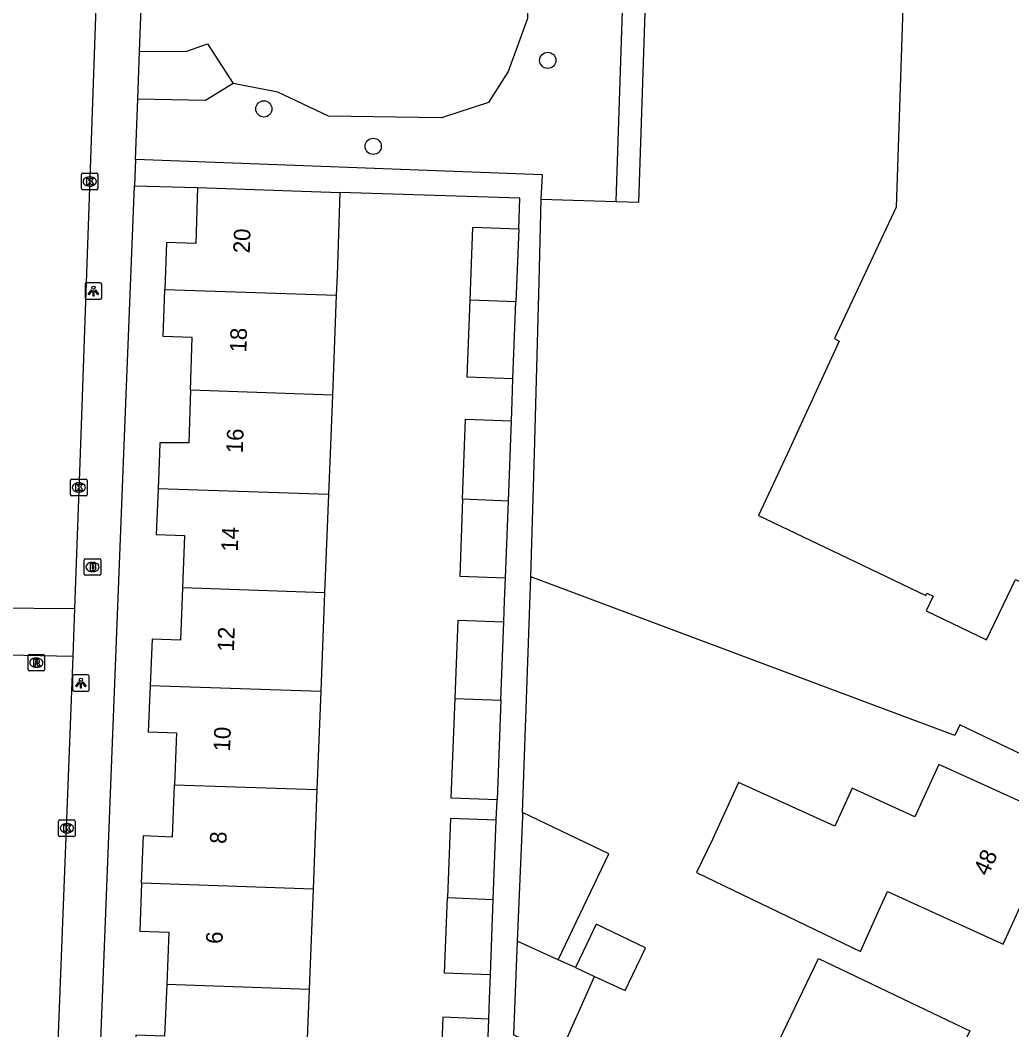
# Model space of a CAD drawing. Extents: x 161355 to 162026, y 386504 to 387459.
# Drawn here: x 161585.7 to 161645.5, y 386965.2 to 387026.1 of the extents above; entities that cross this region are included whole.
import ezdxf

# ---------------------------------------------------------------- set-up
doc = ezdxf.new("R2010")
doc.units = 0
for name, color, linetype in [('IMGEO_Boom', 7, 'Continuous'), ('IMGEO_Brandkraan', 7, 'Continuous'), ('IMGEO_Groenvoorziening', 7, 'Continuous'), ('IMGEO_Kolk', 7, 'Continuous'), ('IMGEO_Lichtpunt', 7, 'Continuous'), ('IMGEO_Pand', 7, 'Continuous'), ('IMGEO_Pand_nummerreeks', 7, 'Continuous'), ('IMGEO_Rijbaan_lokaal_open', 7, 'Continuous'), ('IMGEO_Rioolput', 7, 'Continuous'), ('IMGEO_Voetpad_open', 7, 'Continuous')]:
    doc.layers.add(name, color=color, linetype=linetype)

msp = doc.modelspace()

# ---------------------------------------------------------------- linework, layer by layer
at = {"layer": 'IMGEO_Boom'}
for centre in [(161617.488, 387023.712), (161600.362, 387020.785), (161606.959, 387018.529)]:
    msp.add_circle(centre, 0.489, dxfattribs=at)
at = {"layer": 'IMGEO_Brandkraan'}
for p, q in [((161589.526, 386992.715), (161589.526, 386993.567)), ((161589.601, 386993.641), (161590.453, 386993.641)), ((161590.014, 386993.421), (161590.039, 386993.421)), ((161590.527, 386993.567), (161590.527, 386992.715)), ((161590.453, 386992.641), (161589.601, 386992.641)), ((161590.037, 386992.861), (161590.012, 386992.861))]:
    msp.add_line(p, q, dxfattribs=at)
for points in [[(161589.526, 386992.715), (161589.526, 386993.567)], [(161589.601, 386993.641), (161590.453, 386993.641)], [(161589.874, 386993.341), (161589.874, 386992.941), (161590.087, 386992.941)], [(161590.105, 386993.341), (161589.874, 386993.341)], [(161590.053, 386993.26), (161589.999, 386993.26), (161589.999, 386993.184)], [(161589.999, 386993.184), (161590.052, 386993.184)], [(161590.061, 386993.108), (161589.999, 386993.108), (161589.999, 386993.027)], [(161590.527, 386993.567), (161590.527, 386992.715)], [(161590.453, 386992.641), (161589.601, 386992.641)], [(161589.999, 386993.027), (161590.061, 386993.027)]]:
    msp.add_lwpolyline(points, dxfattribs=at)
for centre, radius, start, end in [((161589.603, 386993.565), 0.0765, 91.55205, 178.44795), ((161589.603, 386993.565), 0.0765, 91.55205, 178.44795), ((161590.054, 386993.222), 0.0379, 267.82845, 90.93552), ((161590.062, 386993.067), 0.0404, 269.87594, 90.50774), ((161590.109, 386993.196), 0.145, 59.4692, 91.53667), ((161590.134, 386993.243), 0.0922, 285.51372, 58.15012), ((161590.139, 386993.051), 0.105, 301.31148, 78.98903), ((161590.451, 386993.565), 0.0765, 1.55205, 88.44795), ((161590.451, 386993.565), 0.0765, 1.55205, 88.44795), ((161589.603, 386992.717), 0.0765, 181.55205, 268.44795), ((161589.603, 386992.717), 0.0765, 181.55205, 268.44795), ((161590.093, 386993.192), 0.251, 268.66757, 293.53466), ((161590.451, 386992.717), 0.0765, 271.55205, 358.44795), ((161590.451, 386992.717), 0.0765, 271.55205, 358.44795)]:
    msp.add_arc(centre, radius, start, end, dxfattribs=at)
for centre, major_axis, ratio, start_param, end_param in [((161590.013, 386993.141), (-0.387, 0.002), 0.722429, 4.712389, 7.853982), ((161590.038, 386993.141), (-0.39, 0.002), 0.717154, 1.570796, 4.712389)]:
    msp.add_ellipse(centre, major_axis=major_axis, ratio=ratio, start_param=start_param, end_param=end_param, dxfattribs=at)
at = {"layer": 'IMGEO_Groenvoorziening'}
for points in [[(161622.376, 387038.848), (161621.592, 387015.198)], [(161616.414, 387030.911), (161616.263, 387026.241), (161615.091, 387023.044), (161613.923, 387021.167), (161611.08, 387020.252), (161604.264, 387020.353), (161601.199, 387021.802), (161598.502, 387022.32)]]:
    msp.add_lwpolyline(points, dxfattribs=at)
at = {"layer": 'IMGEO_Kolk'}
for p, q in [((161589.354, 387015.977), (161589.354, 387016.829)), ((161589.429, 387016.903), (161590.281, 387016.903)), ((161590.355, 387016.829), (161590.355, 387015.977)), ((161589.842, 387016.683), (161589.867, 387016.683)), ((161590.281, 387015.903), (161589.429, 387015.903)), ((161589.865, 387016.123), (161589.84, 387016.123)), ((161588.702, 386997.516), (161588.702, 386998.368)), ((161588.777, 386998.442), (161589.629, 386998.442)), ((161589.19, 386998.222), (161589.215, 386998.222)), ((161589.703, 386998.368), (161589.703, 386997.516)), ((161589.629, 386997.442), (161588.777, 386997.442)), ((161589.213, 386997.662), (161589.188, 386997.662)), ((161588.054, 386977.877), (161588.906, 386977.877)), ((161587.979, 386976.951), (161587.979, 386977.803)), ((161588.467, 386977.657), (161588.492, 386977.657)), ((161588.98, 386977.803), (161588.98, 386976.951)), ((161588.906, 386976.877), (161588.054, 386976.877)), ((161588.49, 386977.097), (161588.465, 386977.097))]:
    msp.add_line(p, q, dxfattribs=at)
for points in [[(161589.354, 387015.977), (161589.354, 387016.829)], [(161589.429, 387016.903), (161590.281, 387016.903)], [(161590.355, 387016.829), (161590.355, 387015.977)], [(161589.675, 387016.603), (161589.798, 387016.603), (161589.798, 387016.452), (161589.928, 387016.603), (161590.092, 387016.603), (161589.946, 387016.452), (161590.099, 387016.203), (161589.947, 387016.203), (161589.862, 387016.367), (161589.798, 387016.3), (161589.798, 387016.203), (161589.675, 387016.203), (161589.675, 387016.603)], [(161590.281, 387015.903), (161589.429, 387015.903)], [(161588.702, 386997.516), (161588.702, 386998.368)], [(161588.777, 386998.442), (161589.629, 386998.442)], [(161589.023, 386998.142), (161589.146, 386998.142), (161589.146, 386997.991), (161589.276, 386998.142), (161589.44, 386998.142), (161589.294, 386997.991), (161589.447, 386997.742), (161589.295, 386997.742), (161589.21, 386997.906), (161589.146, 386997.839), (161589.146, 386997.742), (161589.023, 386997.742), (161589.023, 386998.142)], [(161589.703, 386998.368), (161589.703, 386997.516)], [(161589.629, 386997.442), (161588.777, 386997.442)], [(161588.054, 386977.877), (161588.906, 386977.877)], [(161587.979, 386976.951), (161587.979, 386977.803)], [(161588.3, 386977.577), (161588.423, 386977.577), (161588.423, 386977.426), (161588.553, 386977.577), (161588.717, 386977.577), (161588.571, 386977.426), (161588.724, 386977.177), (161588.572, 386977.177), (161588.487, 386977.341), (161588.423, 386977.274), (161588.423, 386977.177), (161588.3, 386977.177), (161588.3, 386977.577)], [(161588.98, 386977.803), (161588.98, 386976.951)], [(161588.906, 386976.877), (161588.054, 386976.877)]]:
    msp.add_lwpolyline(points, dxfattribs=at)
for centre, start, end in [((161589.431, 387016.827), 91.55205, 178.44795), ((161589.431, 387016.827), 91.55205, 178.44795), ((161590.279, 387016.827), 1.55205, 88.44795), ((161590.279, 387016.827), 1.55205, 88.44795), ((161589.431, 387015.979), 181.55205, 268.44795), ((161589.431, 387015.979), 181.55205, 268.44795), ((161590.279, 387015.979), 271.55205, 358.44795), ((161590.279, 387015.979), 271.55205, 358.44795), ((161588.779, 386998.366), 91.55205, 178.44795), ((161588.779, 386998.366), 91.55205, 178.44795), ((161589.627, 386998.366), 1.55205, 88.44795), ((161589.627, 386998.366), 1.55205, 88.44795), ((161588.779, 386997.518), 181.55205, 268.44795), ((161588.779, 386997.518), 181.55205, 268.44795), ((161589.627, 386997.518), 271.55205, 358.44795), ((161589.627, 386997.518), 271.55205, 358.44795), ((161588.056, 386977.801), 91.55205, 178.44795), ((161588.056, 386977.801), 91.55205, 178.44795), ((161588.904, 386977.801), 1.55205, 88.44795), ((161588.904, 386977.801), 1.55205, 88.44795), ((161588.056, 386976.953), 181.55205, 268.44795), ((161588.056, 386976.953), 181.55205, 268.44795), ((161588.904, 386976.953), 271.55205, 358.44795), ((161588.904, 386976.953), 271.55205, 358.44795)]:
    msp.add_arc(centre, 0.0765, start, end, dxfattribs=at)
for centre, major_axis, ratio, start_param, end_param in [((161589.841, 387016.403), (-0.387, 0.002), 0.722429, 4.712389, 7.853982), ((161589.866, 387016.403), (-0.39, 0.002), 0.717154, 1.570796, 4.712389), ((161589.189, 386997.942), (-0.387, 0.002), 0.722429, 4.712389, 7.853982), ((161589.214, 386997.942), (-0.39, 0.002), 0.717154, 1.570796, 4.712389), ((161588.466, 386977.377), (-0.387, 0.002), 0.722429, 4.712389, 7.853982), ((161588.491, 386977.377), (-0.39, 0.002), 0.717154, 1.570796, 4.712389)]:
    msp.add_ellipse(centre, major_axis=major_axis, ratio=ratio, start_param=start_param, end_param=end_param, dxfattribs=at)
at = {"layer": 'IMGEO_Lichtpunt'}
for p, q in [((161589.583, 387010.2), (161589.583, 387009.393)), ((161589.583, 387010.2), (161589.583, 387009.393)), ((161590.485, 387010.295), (161589.677, 387010.295)), ((161590.485, 387010.295), (161589.677, 387010.295)), ((161590.579, 387009.393), (161590.579, 387010.2)), ((161590.579, 387009.393), (161590.579, 387010.2)), ((161589.677, 387009.299), (161590.485, 387009.299)), ((161589.677, 387009.299), (161590.485, 387009.299)), ((161588.825, 386986.544), (161588.825, 386985.737)), ((161588.825, 386986.544), (161588.825, 386985.737)), ((161589.727, 386986.639), (161588.919, 386986.639)), ((161589.727, 386986.639), (161588.919, 386986.639)), ((161589.821, 386985.737), (161589.821, 386986.544)), ((161589.821, 386985.737), (161589.821, 386986.544)), ((161588.919, 386985.643), (161589.727, 386985.643)), ((161588.919, 386985.643), (161589.727, 386985.643))]:
    msp.add_line(p, q, dxfattribs=at)
for points in [[(161589.957, 387009.864), (161589.996, 387009.836), (161589.808, 387009.574), (161589.77, 387009.601), (161589.957, 387009.864)], [(161590.059, 387009.816), (161590.106, 387009.816), (161590.106, 387009.494), (161590.059, 387009.494), (161590.059, 387009.816)], [(161590.169, 387009.836), (161590.207, 387009.863), (161590.394, 387009.601), (161590.355, 387009.573), (161590.169, 387009.836)], [(161589.199, 386986.208), (161589.238, 386986.18), (161589.05, 386985.918), (161589.012, 386985.945), (161589.199, 386986.208)], [(161589.301, 386986.16), (161589.348, 386986.16), (161589.348, 386985.838), (161589.301, 386985.838), (161589.301, 386986.16)], [(161589.411, 386986.18), (161589.449, 386986.207), (161589.636, 386985.945), (161589.597, 386985.917), (161589.411, 386986.18)]]:
    msp.add_lwpolyline(points, dxfattribs=at)
for centre in [(161590.082, 387009.998), (161589.324, 386986.342)]:
    msp.add_circle(centre, 0.0994, dxfattribs=at)
for centre, start, end in [((161589.677, 387010.2), 90, 180), ((161589.677, 387010.2), 90, 180), ((161590.485, 387010.2), 0, 90), ((161590.485, 387010.2), 0, 90), ((161589.677, 387009.393), 180, 270), ((161589.677, 387009.393), 180, 270), ((161590.485, 387009.393), 270, 0), ((161590.485, 387009.393), 270, 360), ((161588.919, 386986.544), 90, 180), ((161588.919, 386986.544), 90, 180), ((161589.727, 386986.544), 0, 90), ((161589.727, 386986.544), 0, 90), ((161588.919, 386985.737), 180, 270), ((161588.919, 386985.737), 180, 270), ((161589.727, 386985.737), 270, 0), ((161589.727, 386985.737), 270, 360)]:
    msp.add_arc(centre, 0.0946, start, end, dxfattribs=at)
at = {"layer": 'IMGEO_Pand'}
for points in [[(161621.592, 387015.198), (161622.991, 387015.152), (161623.69, 387036.251)], [(161639.028, 387030.532), (161638.508, 387014.846), (161634.791, 387006.94), (161635.073, 387006.762), (161631.945, 387000), (161630.209, 386996.251), (161636.023, 386993.468), (161640.299, 386991.421), (161640.365, 386991.559), (161640.742, 386991.379), (161640.319, 386990.494), (161643.964, 386988.749), (161645.705, 386992.384), (161649.5, 386990.567), (161654.01, 386988.408), (161653.819, 386988.01), (161653.371, 386988.225), (161651.645, 386984.62), (161652.067, 386984.418), (161649.94, 386979.976), (161642.34, 386983.614), (161642.038, 386982.983), (161637.356, 386984.735), (161616.468, 386992.553)], [(161596.365, 387016.033), (161596.254, 387012.669), (161594.482, 387012.728), (161594.389, 387009.89)], [(161596.365, 387016.033), (161604.946, 387015.749)], [(161604.946, 387015.749), (161604.776, 387010.752), (161604.729, 387009.538)], [(161616.468, 386992.553), (161616.68, 387000), (161616.974, 387010.349), (161617.094, 387015.347)], [(161617.094, 387015.347), (161621.592, 387015.198)], [(161612.806, 387009.251), (161612.973, 387013.654), (161615.735, 387013.549)], [(161615.735, 387013.549), (161615.568, 387009.14)], [(161595.932, 387003.812), (161596.037, 387006.992), (161594.295, 387007.05), (161594.389, 387009.89)], [(161594.389, 387009.89), (161604.729, 387009.538)], [(161604.729, 387009.538), (161604.494, 387003.521)], [(161615.392, 387004.487), (161612.63, 387004.591), (161612.806, 387009.251)], [(161615.568, 387009.14), (161612.806, 387009.251)], [(161615.392, 387004.487), (161615.568, 387009.14)], [(161595.932, 387003.812), (161595.827, 387000.633), (161594.088, 387000.625), (161594.064, 387000), (161593.981, 386997.865)], [(161604.494, 387003.521), (161595.932, 387003.812)], [(161604.494, 387003.521), (161604.356, 387000), (161604.259, 386997.515)], [(161612.351, 386997.232), (161612.534, 387002.06), (161615.297, 387001.956)], [(161615.114, 386997.121), (161615.297, 387001.956)], [(161593.981, 386997.865), (161593.873, 386995.106), (161595.582, 386995.037), (161595.454, 386991.878)], [(161604.259, 386997.515), (161593.981, 386997.865)], [(161604.259, 386997.515), (161604.027, 386991.586)], [(161612.351, 386997.232), (161612.176, 386992.596), (161614.938, 386992.492)], [(161615.114, 386997.121), (161612.351, 386997.232)], [(161614.938, 386992.492), (161615.114, 386997.121)], [(161595.454, 386991.878), (161595.327, 386988.721), (161593.616, 386988.79), (161593.503, 386985.995)], [(161604.027, 386991.586), (161595.454, 386991.878)], [(161604.027, 386991.586), (161603.795, 386985.645)], [(161611.896, 386985.213), (161612.075, 386989.938), (161614.838, 386989.834)], [(161614.659, 386985.102), (161614.838, 386989.834)], [(161593.503, 386985.995), (161593.391, 386983.201), (161595.1, 386983.132), (161594.973, 386980)], [(161593.503, 386985.995), (161603.795, 386985.645)], [(161603.795, 386985.645), (161603.563, 386979.708)], [(161614.431, 386979.092), (161611.669, 386979.203), (161611.896, 386985.213)], [(161611.896, 386985.213), (161614.659, 386985.102)], [(161614.659, 386985.102), (161614.431, 386979.092)], [(161648.381, 386977.91), (161643.83, 386979.98), (161641.076, 386981.232), (161639.638, 386978.068), (161635.853, 386979.789), (161634.812, 386977.499), (161628.998, 386980.143), (161627.426, 386976.709), (161626.462, 386974.71), (161636.348, 386969.941), (161637.37, 386972.188), (161637.992, 386973.556), (161644.961, 386970.388), (161648.381, 386977.91)], [(161592.989, 386974.058), (161593.105, 386976.94), (161594.847, 386976.869), (161594.973, 386980)], [(161594.973, 386980), (161603.563, 386979.708)], [(161603.563, 386979.708), (161603.329, 386973.706)], [(161614.384, 386977.857), (161611.622, 386977.961), (161611.441, 386973.194)], [(161614.204, 386973.082), (161614.384, 386977.857)], [(161615.966, 386978.319), (161615.957, 386978.067), (161615.651, 386970.572)], [(161618.108, 386969.444), (161621.174, 386975.836), (161615.966, 386978.319)], [(161592.989, 386974.058), (161592.873, 386971.177), (161594.629, 386971.106), (161594.503, 386967.968)], [(161603.329, 386973.706), (161592.989, 386974.058)], [(161603.329, 386973.706), (161603.093, 386967.675)], [(161614.031, 386968.526), (161611.269, 386968.631), (161611.441, 386973.194)], [(161611.441, 386973.194), (161614.204, 386973.082)], [(161614.031, 386968.526), (161614.204, 386973.082)], [(161620.307, 386968.436), (161622.162, 386967.584), (161623.073, 386969.484), (161623.148, 386969.64), (161623.395, 386970.155), (161620.411, 386971.587), (161620.065, 386970.866), (161619.153, 386968.966)], [(161615.651, 386970.572), (161615.424, 386964.911)], [(161618.108, 386969.444), (161615.651, 386970.572)], [(161619.153, 386968.966), (161618.108, 386969.444)], [(161630.988, 386963.597), (161633.814, 386969.52), (161636.937, 386968.03), (161638.448, 386967.309), (161642.96, 386965.155), (161640.132, 386959.232)], [(161619.153, 386968.966), (161620.307, 386968.436)], [(161615.424, 386964.911), (161618.2, 386963.681), (161620.307, 386968.436)], [(161594.503, 386967.968), (161594.376, 386964.828), (161592.644, 386964.898), (161592.531, 386962.095)], [(161594.503, 386967.968), (161603.093, 386967.675)], [(161603.093, 386967.675), (161602.861, 386961.743)], [(161613.93, 386965.865), (161611.168, 386965.97), (161610.986, 386961.175)], [(161613.749, 386961.064), (161613.93, 386965.865)]]:
    msp.add_lwpolyline(points, dxfattribs=at)
at = {"layer": 'IMGEO_Rijbaan_lokaal_open'}
for points in [[(161590.57, 387036.678), (161589.274, 387000), (161588.945, 386990.639)], [(161584.008, 386990.687), (161588.945, 386990.639)], [(161588.945, 386990.639), (161588.842, 386987.732)], [(161588.842, 386987.732), (161583.884, 386987.851)], [(161588.842, 386987.732), (161587.588, 386955.655)]]:
    msp.add_lwpolyline(points, dxfattribs=at)
at = {"layer": 'IMGEO_Rioolput'}
for p, q in [((161586.134, 386986.944), (161586.134, 386987.796)), ((161586.209, 386987.87), (161587.061, 386987.87)), ((161586.622, 386987.65), (161586.647, 386987.65)), ((161587.135, 386987.796), (161587.135, 386986.944)), ((161586.645, 386987.09), (161586.62, 386987.09)), ((161587.061, 386986.87), (161586.209, 386986.87))]:
    msp.add_line(p, q, dxfattribs=at)
for points in [[(161586.134, 386986.944), (161586.134, 386987.796)], [(161586.209, 386987.87), (161587.061, 386987.87)], [(161587.135, 386987.796), (161587.135, 386986.944)], [(161586.723, 386987.568), (161586.471, 386987.57), (161586.471, 386987.17)], [(161586.471, 386987.17), (161586.595, 386987.17), (161586.595, 386987.332), (161586.606, 386987.332)], [(161586.649, 386987.489), (161586.595, 386987.489), (161586.595, 386987.408)], [(161586.595, 386987.408), (161586.647, 386987.408)], [(161586.653, 386987.303), (161586.724, 386987.17), (161586.864, 386987.17), (161586.799, 386987.296)], [(161587.061, 386986.87), (161586.209, 386986.87)]]:
    msp.add_lwpolyline(points, dxfattribs=at)
for centre, radius, start, end in [((161586.211, 386987.794), 0.0765, 91.55205, 178.44795), ((161586.211, 386987.794), 0.0765, 91.55205, 178.44795), ((161587.059, 386987.794), 0.0765, 1.55205, 88.44795), ((161587.059, 386987.794), 0.0765, 1.55205, 88.44795), ((161586.605, 386987.279), 0.0533, 26.02933, 88.69889), ((161586.631, 386987.597), 0.19, 274.7715, 282.96867), ((161586.655, 386987.393), 0.0964, 77.00612, 93.18647), ((161586.669, 386987.45), 0.0378, 276.66336, 79.67722), ((161586.722, 386987.458), 0.109, 350.36119, 89.41601), ((161586.72, 386987.458), 0.112, 277.58423, 350.98172), ((161586.704, 386987.243), 0.108, 29.51342, 73.79051), ((161586.211, 386986.946), 0.0765, 181.55205, 268.44795), ((161586.211, 386986.946), 0.0765, 181.55205, 268.44795), ((161587.059, 386986.946), 0.0765, 271.55205, 358.44795), ((161587.059, 386986.946), 0.0765, 271.55205, 358.44795)]:
    msp.add_arc(centre, radius, start, end, dxfattribs=at)
for centre, major_axis, ratio, start_param, end_param in [((161586.621, 386987.37), (-0.387, 0.002), 0.722429, 4.712389, 7.853982), ((161586.646, 386987.37), (-0.39, 0.002), 0.717154, 1.570796, 4.712389)]:
    msp.add_ellipse(centre, major_axis=major_axis, ratio=ratio, start_param=start_param, end_param=end_param, dxfattribs=at)
at = {"layer": 'IMGEO_Voetpad_open'}
for points in [[(161592.862, 387024.247), (161593.384, 387037.931)], [(161592.752, 387021.38), (161592.862, 387024.247)], [(161592.862, 387024.247), (161595.709, 387024.261), (161596.972, 387024.714), (161598.502, 387022.32)], [(161598.502, 387022.32), (161596.85, 387021.3), (161592.752, 387021.38)], [(161592.613, 387017.724), (161592.752, 387021.38)], [(161592.613, 387017.724), (161592.551, 387016.152)], [(161617.094, 387015.347), (161617.166, 387016.808), (161592.613, 387017.724)], [(161590.19, 386955.861), (161591.919, 387000), (161592.551, 387016.152)], [(161592.551, 387016.152), (161596.365, 387016.033)], [(161615.735, 387013.549), (161615.804, 387015.39), (161604.946, 387015.749)], [(161615.297, 387001.956), (161615.341, 387003.131), (161615.392, 387004.487)], [(161614.838, 386989.834), (161614.886, 386991.111), (161614.938, 386992.492)], [(161615.966, 386978.319), (161616.468, 386992.553)], [(161614.384, 386977.857), (161614.431, 386979.092)], [(161613.93, 386965.865), (161613.976, 386967.073), (161614.031, 386968.526)]]:
    msp.add_lwpolyline(points, dxfattribs=at)

# ---------------------------------------------------------------- texts
at = {"layer": 'IMGEO_Pand_nummerreeks'}
for s, rotation, p in [('20', 88.01614, (161599.509, 387012.059)), ('18', 88.01614, (161599.302, 387006.074)), ('16', 88.01614, (161599.091, 386999.995)), ('14', 87.76246, (161598.789, 386994.057)), ('12', 87.76246, (161598.553, 386988.022)), ('10', 87.76246, (161598.317, 386981.996)), ('8', 87.76246, (161598.1, 386976.424)), ('48', 65.5521, (161644.036, 386974.442)), ('6', 87.76246, (161597.864, 386970.388))]:
    msp.add_text(s, height=1, rotation=rotation, dxfattribs=at).set_placement(p)

doc.saveas('drawing.dxf')
